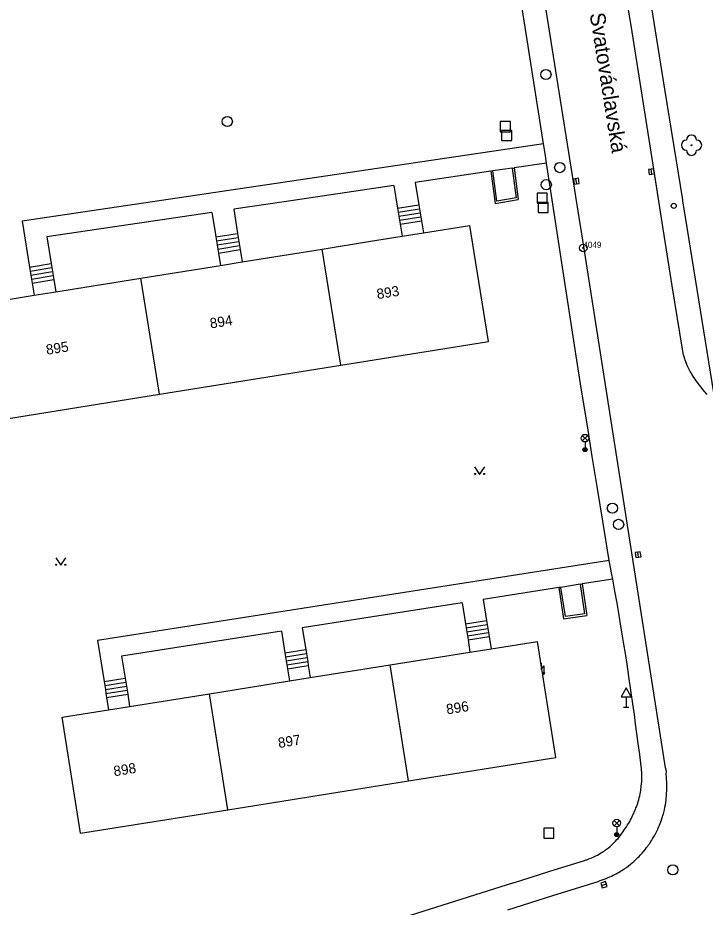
# Model space of a CAD drawing. Extents: x -539244 to -537359, y -1183785 to -1181851.
# Drawn here: x -537658.7 to -537591.1, y -1182068.9 to -1181981.5 of the extents above; entities that cross this region are included whole.
import ezdxf

# ---------------------------------------------------------------- set-up
doc = ezdxf.new("R2010")
doc.units = 0
for name, color, linetype in [('Vrstva 10', 7, 'Continuous'), ('Vrstva 11', 7, 'Continuous'), ('Vrstva 21', 7, 'Continuous'), ('Vrstva 22', 7, 'Continuous'), ('Vrstva 23', 7, 'Continuous'), ('Vrstva 24', 7, 'Continuous'), ('Vrstva 26', 7, 'Continuous'), ('Vrstva 27', 7, 'Continuous'), ('Vrstva 28', 7, 'Continuous'), ('Vrstva 33', 7, 'Continuous'), ('Vrstva 34', 7, 'Continuous'), ('Vrstva 36', 7, 'Continuous'), ('Vrstva 47', 7, 'Continuous'), ('Vrstva 49', 7, 'Continuous'), ('Vrstva 5', 7, 'Continuous'), ('Vrstva 7', 7, 'Continuous')]:
    doc.layers.add(name, color=color, linetype=linetype)

msp = doc.modelspace()

# ---------------------------------------------------------------- linework, layer by layer
at = {"layer": 'Vrstva 10'}
for p, q in [((-537598.321, -1181982.879), (-537600.408, -1181969.81)), ((-537604.08, -1181997.63), (-537607.495, -1181976.195)), ((-537596.931, -1181991.591), (-537598.321, -1181982.879)), ((-537596.14, -1181996.57), (-537596.931, -1181991.591)), ((-537594.356, -1182007.847), (-537595.341, -1182001.615)), ((-537599.455, -1182026.989), (-537603.168, -1182003.365)), ((-537593.37, -1182014.08), (-537594.356, -1182007.847)), ((-537595.733, -1182050.613), (-537599.455, -1182026.989)), ((-537595.024, -1182055.239), (-537595.733, -1182050.613))]:
    msp.add_line(p, q, dxfattribs=at)
for points in [[(-537595.341, -1182001.615), (-537595.74, -1181999.092), (-537596.14, -1181996.57)], [(-537603.168, -1182003.365), (-537603.335, -1182002.313), (-537603.393, -1182001.946), (-537603.624, -1182000.497), (-537604.08, -1181997.63)], [(-537590.921, -1182018.529), (-537591.144, -1182018.275), (-537591.348, -1182018.035), (-537591.534, -1182017.808), (-537591.703, -1182017.595), (-537591.856, -1182017.393), (-537591.996, -1182017.202), (-537592.122, -1182017.021), (-537592.237, -1182016.851), (-537592.34, -1182016.69), (-537592.434, -1182016.538), (-537592.519, -1182016.394), (-537592.596, -1182016.258), (-537592.665, -1182016.13), (-537592.728, -1182016.009), (-537592.785, -1182015.895), (-537592.887, -1182015.679), (-537592.969, -1182015.488), (-537593.036, -1182015.318), (-537593.092, -1182015.169), (-537593.137, -1182015.037), (-537593.174, -1182014.92), (-537593.234, -1182014.714), (-537593.274, -1182014.558), (-537593.302, -1182014.44), (-537593.338, -1182014.261), (-537593.37, -1182014.08)], [(-537595.004, -1182058.627), (-537594.976, -1182058.416), (-537594.954, -1182058.217), (-537594.936, -1182058.031), (-537594.923, -1182057.857), (-537594.913, -1182057.694), (-537594.906, -1182057.54), (-537594.898, -1182057.253), (-537594.897, -1182057.001), (-537594.901, -1182056.781), (-537594.907, -1182056.589), (-537594.915, -1182056.42), (-537594.933, -1182056.125), (-537594.951, -1182055.903), (-537594.94, -1182055.55), (-537595.024, -1182055.239)], [(-537601.045, -1182066.175), (-537600.856, -1182066.101), (-537600.675, -1182066.025), (-537600.501, -1182065.948), (-537600.333, -1182065.87), (-537600.173, -1182065.792), (-537600.019, -1182065.713), (-537599.871, -1182065.635), (-537599.729, -1182065.556), (-537599.592, -1182065.478), (-537599.461, -1182065.399), (-537599.335, -1182065.321), (-537599.215, -1182065.244), (-537599.099, -1182065.167), (-537598.877, -1182065.013), (-537598.673, -1182064.862), (-537598.484, -1182064.715), (-537598.311, -1182064.573), (-537598.151, -1182064.435), (-537598.003, -1182064.302), (-537597.866, -1182064.174), (-537597.74, -1182064.051), (-537597.624, -1182063.933), (-537597.516, -1182063.82), (-537597.417, -1182063.712), (-537597.324, -1182063.609), (-537597.155, -1182063.411), (-537597.01, -1182063.232), (-537596.885, -1182063.073), (-537596.779, -1182062.93), (-537596.687, -1182062.802), (-537596.608, -1182062.689), (-537596.473, -1182062.487), (-537596.374, -1182062.332), (-537596.301, -1182062.214), (-537596.194, -1182062.034), (-537596.09, -1182061.85), (-537595.979, -1182061.644), (-537595.877, -1182061.444), (-537595.785, -1182061.251), (-537595.7, -1182061.064), (-537595.622, -1182060.882), (-537595.551, -1182060.706), (-537595.486, -1182060.536), (-537595.427, -1182060.371), (-537595.373, -1182060.21), (-537595.324, -1182060.055), (-537595.279, -1182059.905), (-537595.238, -1182059.76), (-537595.201, -1182059.619), (-537595.167, -1182059.482), (-537595.137, -1182059.35), (-537595.083, -1182059.093), (-537595.039, -1182058.853), (-537595.004, -1182058.627)], [(-537610.52, -1182069.18), (-537606.09, -1182067.785), (-537601.66, -1182066.39), (-537601.447, -1182066.32), (-537601.242, -1182066.249), (-537601.045, -1182066.175)]]:
    msp.add_lwpolyline(points, dxfattribs=at)
at = {"layer": 'Vrstva 11'}
for p, q in [((-537608.814, -1181982.429), (-537609.977, -1181975.131)), ((-537595.086, -1181988.527), (-537597.11, -1181975.95)), ((-537608.155, -1181986.6), (-537608.814, -1181982.429)), ((-537607.01, -1181993.91), (-537658.271, -1182001.498)), ((-537606.73, -1181995.78), (-537609.904, -1181996.25)), ((-537612.2, -1181996.59), (-537619.625, -1181997.689)), ((-537610.102, -1181996.279), (-537612.002, -1181996.561)), ((-537619.625, -1181997.689), (-537619.274, -1181999.876)), ((-537621.724, -1181998), (-537632.52, -1181999.598)), ((-537621.724, -1181998), (-537621.369, -1182000.212)), ((-537632.52, -1181999.598), (-537637.473, -1182000.331)), ((-537637.473, -1182000.331), (-537637.093, -1182002.704)), ((-537621.369, -1182000.212), (-537619.274, -1181999.876)), ((-537621.305, -1182000.606), (-537619.21, -1182000.27)), ((-537639.629, -1182000.65), (-537655.843, -1182003.051)), ((-537639.629, -1182000.65), (-537639.32, -1182002.575)), ((-537621.242, -1182001.001), (-537619.147, -1182000.665)), ((-537621.178, -1182001.396), (-537619.083, -1182001.06)), ((-537591.591, -1182010.248), (-537593.062, -1182001.105)), ((-537658.271, -1182001.498), (-537657.548, -1182006.006)), ((-537621.115, -1182001.791), (-537619.02, -1182001.455)), ((-537655.843, -1182003.051), (-537655.424, -1182005.665)), ((-537639.32, -1182002.575), (-537639.244, -1182003.049)), ((-537639.244, -1182003.049), (-537637.093, -1182002.704)), ((-537639.181, -1182003.443), (-537637.029, -1182003.098)), ((-537639.118, -1182003.838), (-537636.966, -1182003.493)), ((-537639.054, -1182004.233), (-537636.903, -1182003.888)), ((-537604.904, -1182007.716), (-537605.491, -1182003.885)), ((-537638.991, -1182004.628), (-537636.839, -1182004.283)), ((-537657.548, -1182006.006), (-537655.424, -1182005.665)), ((-537657.484, -1182006.4), (-537655.36, -1182006.059)), ((-537657.421, -1182006.795), (-537655.297, -1182006.454)), ((-537657.357, -1182007.19), (-537655.236, -1182006.843)), ((-537657.294, -1182007.585), (-537655.17, -1182007.244)), ((-537590.12, -1182019.39), (-537591.591, -1182010.248)), ((-537600.57, -1182034.84), (-537650.874, -1182042.716)), ((-537603.406, -1182037.189), (-537605.322, -1182037.489)), ((-537600.22, -1182036.69), (-537603.209, -1182037.158)), ((-537605.52, -1182037.52), (-537612.954, -1182038.684)), ((-537612.954, -1182038.684), (-537612.624, -1182040.753)), ((-537615.029, -1182039.009), (-537620.698, -1182039.896)), ((-537615.029, -1182039.009), (-537614.698, -1182041.084)), ((-537620.698, -1182039.896), (-537630.737, -1182041.468)), ((-537630.737, -1182041.468), (-537630.399, -1182043.588)), ((-537614.698, -1182041.084), (-537612.624, -1182040.753)), ((-537614.634, -1182041.479), (-537612.56, -1182041.148)), ((-537614.571, -1182041.874), (-537612.497, -1182041.543)), ((-537632.794, -1182041.79), (-537648.503, -1182044.249)), ((-537632.794, -1182041.79), (-537632.455, -1182043.916)), ((-537614.508, -1182042.269), (-537612.434, -1182041.938)), ((-537614.445, -1182042.664), (-537612.371, -1182042.333)), ((-537650.874, -1182042.716), (-537650.23, -1182046.751)), ((-537632.455, -1182043.916), (-537630.399, -1182043.588)), ((-537632.391, -1182044.311), (-537630.335, -1182043.983)), ((-537648.503, -1182044.249), (-537648.156, -1182046.42)), ((-537632.328, -1182044.706), (-537630.272, -1182044.378)), ((-537632.265, -1182045.101), (-537630.209, -1182044.773)), ((-537632.202, -1182045.496), (-537630.146, -1182045.168)), ((-537650.23, -1182046.751), (-537648.156, -1182046.42)), ((-537650.166, -1182047.146), (-537648.092, -1182046.815)), ((-537650.103, -1182047.541), (-537648.029, -1182047.21)), ((-537650.04, -1182047.936), (-537647.966, -1182047.605)), ((-537649.977, -1182048.331), (-537647.903, -1182048)), ((-537609.98, -1182066.54), (-537632.97, -1182073.77))]:
    msp.add_line(p, q, dxfattribs=at)
for points in [[(-537606.869, -1181994.845), (-537607.01, -1181993.91), (-537607.406, -1181991.367), (-537608.155, -1181986.6)], [(-537593.062, -1182001.105), (-537593.318, -1181999.513), (-537593.335, -1181999.41), (-537595.086, -1181988.527)], [(-537605.491, -1182003.885), (-537606.112, -1181999.833), (-537606.73, -1181995.78), (-537606.869, -1181994.845)], [(-537621.369, -1182000.212), (-537621.305, -1182000.606), (-537621.242, -1182001.001), (-537621.178, -1182001.396), (-537621.115, -1182001.791), (-537620.925, -1182002.977)], [(-537619.274, -1181999.876), (-537619.21, -1182000.27), (-537619.147, -1182000.665), (-537619.083, -1182001.06), (-537619.02, -1182001.455), (-537618.831, -1182002.641)], [(-537639.244, -1182003.049), (-537639.181, -1182003.443), (-537639.118, -1182003.838), (-537639.054, -1182004.233), (-537638.991, -1182004.628), (-537638.796, -1182005.843)], [(-537637.093, -1182002.704), (-537637.029, -1182003.098), (-537636.966, -1182003.493), (-537636.903, -1182003.888), (-537636.839, -1182004.283), (-537636.644, -1182005.498)], [(-537655.424, -1182005.665), (-537655.36, -1182006.059), (-537655.297, -1182006.454), (-537655.236, -1182006.843), (-537655.17, -1182007.244), (-537654.979, -1182008.439)], [(-537657.548, -1182006.006), (-537657.484, -1182006.4), (-537657.421, -1182006.795), (-537657.357, -1182007.19), (-537657.294, -1182007.585), (-537657.103, -1182008.78)], [(-537602.646, -1182022.036), (-537603.37, -1182017.501), (-537603.908, -1182014.098), (-537604.308, -1182011.545), (-537604.904, -1182007.716)], [(-537600.57, -1182034.84), (-537601.201, -1182030.973), (-537601.751, -1182027.589), (-537602.229, -1182024.628), (-537602.646, -1182022.036)], [(-537598.807, -1182045.042), (-537598.969, -1182043.996), (-537599.114, -1182043.08), (-537599.244, -1182042.28), (-537599.476, -1182040.88), (-537599.655, -1182039.831), (-537599.793, -1182039.045), (-537600.003, -1182037.867), (-537600.22, -1182036.69), (-537600.309, -1182036.228), (-537600.445, -1182035.535), (-537600.51, -1182035.188), (-537600.57, -1182034.84)], [(-537614.698, -1182041.084), (-537614.634, -1182041.479), (-537614.571, -1182041.874), (-537614.508, -1182042.269), (-537614.445, -1182042.664), (-537614.256, -1182043.858)], [(-537612.624, -1182040.753), (-537612.56, -1182041.148), (-537612.497, -1182041.543), (-537612.434, -1182041.938), (-537612.371, -1182042.333), (-537612.182, -1182043.527)], [(-537632.455, -1182043.916), (-537632.391, -1182044.311), (-537632.328, -1182044.706), (-537632.265, -1182045.101), (-537632.202, -1182045.496), (-537632.012, -1182046.69)], [(-537630.399, -1182043.588), (-537630.335, -1182043.983), (-537630.272, -1182044.378), (-537630.209, -1182044.773), (-537630.146, -1182045.168), (-537629.957, -1182046.363)], [(-537597.42, -1182055.08), (-537597.565, -1182053.931), (-537597.704, -1182052.853), (-537597.837, -1182051.841), (-537597.965, -1182050.893), (-537598.086, -1182050.004), (-537598.202, -1182049.17), (-537598.425, -1182047.607), (-537598.626, -1182046.239), (-537598.807, -1182045.042)], [(-537650.23, -1182046.751), (-537650.166, -1182047.146), (-537650.103, -1182047.541), (-537650.04, -1182047.936), (-537649.977, -1182048.331), (-537649.787, -1182049.526)], [(-537648.156, -1182046.42), (-537648.092, -1182046.815), (-537648.029, -1182047.21), (-537647.966, -1182047.605), (-537647.903, -1182048), (-537647.713, -1182049.195)], [(-537600.72, -1182063.16), (-537600.633, -1182063.09), (-537600.47, -1182062.953), (-537600.329, -1182062.829), (-537600.208, -1182062.715), (-537600.103, -1182062.612), (-537600.012, -1182062.519), (-537599.933, -1182062.436), (-537599.797, -1182062.285), (-537599.696, -1182062.168), (-537599.621, -1182062.078), (-537599.509, -1182061.939), (-537599.399, -1182061.795), (-537599.251, -1182061.593), (-537599.113, -1182061.397), (-537598.984, -1182061.206), (-537598.863, -1182061.021), (-537598.751, -1182060.841), (-537598.647, -1182060.666), (-537598.55, -1182060.497), (-537598.459, -1182060.332), (-537598.375, -1182060.172), (-537598.296, -1182060.017), (-537598.223, -1182059.866), (-537598.155, -1182059.72), (-537598.092, -1182059.578), (-537598.033, -1182059.44), (-537597.979, -1182059.307), (-537597.928, -1182059.177), (-537597.881, -1182059.052), (-537597.795, -1182058.808), (-537597.722, -1182058.578), (-537597.66, -1182058.363), (-537597.606, -1182058.16), (-537597.561, -1182057.97), (-537597.522, -1182057.791), (-537597.49, -1182057.624), (-537597.462, -1182057.466), (-537597.44, -1182057.318), (-537597.421, -1182057.18), (-537597.405, -1182057.049), (-537597.381, -1182056.805), (-537597.367, -1182056.59), (-537597.358, -1182056.402), (-537597.355, -1182056.238), (-537597.354, -1182056.094), (-537597.359, -1182055.841), (-537597.368, -1182055.651), (-537597.377, -1182055.508), (-537597.396, -1182055.294), (-537597.42, -1182055.08)], [(-537609.98, -1182066.54), (-537606.49, -1182065.435), (-537603, -1182064.33), (-537602.869, -1182064.288), (-537602.77, -1182064.26), (-537602.505, -1182064.157), (-537602.284, -1182064.068), (-537602.08, -1182063.979), (-537601.892, -1182063.891), (-537601.719, -1182063.803), (-537601.558, -1182063.716), (-537601.41, -1182063.63), (-537601.272, -1182063.546), (-537601.145, -1182063.464), (-537601.027, -1182063.385), (-537600.917, -1182063.307), (-537600.815, -1182063.232), (-537600.72, -1182063.16)]]:
    msp.add_lwpolyline(points, dxfattribs=at)
at = {"layer": 'Vrstva 21'}
for radius in [0.375, 0.05]:
    msp.add_circle((-537603.11, -1182004.12), radius, dxfattribs=at)
at = {"layer": 'Vrstva 22'}
msp.add_circle((-537592.47, -1181994.03), 0.05, dxfattribs=at)
for centre, start, end in [((-537592.47, -1181993.53), 0, 180), ((-537592.97, -1181994.03), 90, 270), ((-537591.97, -1181994.03), 270, 90), ((-537592.47, -1181994.53), 180, 0)]:
    msp.add_arc(centre, 0.5, start, end, dxfattribs=at)
at = {"layer": 'Vrstva 24'}
for p, q in [((-537607.25, -1182044.944), (-537607.25, -1182045.571)), ((-537607.25, -1182045.571), (-537607, -1182045.195)), ((-537607.109, -1182045.825), (-537607, -1182046.07)), ((-537607, -1182045.195), (-537607, -1182046.07)), ((-537607, -1182046.07), (-537606.889, -1182045.825))]:
    msp.add_line(p, q, dxfattribs=at)
at = {"layer": 'Vrstva 26'}
for points in [[(-537611.269, -1181992.71), (-537610.27, -1181992.709), (-537610.271, -1181991.71), (-537611.27, -1181991.711)], [(-537611.139, -1181993.58), (-537610.14, -1181993.579), (-537610.141, -1181992.58), (-537611.14, -1181992.581)], [(-537607.649, -1181999.73), (-537606.65, -1181999.729), (-537606.651, -1181998.73), (-537607.65, -1181998.731)], [(-537607.559, -1182000.66), (-537606.56, -1182000.659), (-537606.561, -1181999.66), (-537607.56, -1181999.661)], [(-537606.989, -1182062.149), (-537605.991, -1182062.149), (-537605.991, -1182061.149), (-537606.989, -1182061.149)]]:
    msp.add_lwpolyline(points, close=True, dxfattribs=at)
at = {"layer": 'Vrstva 27'}
for p, q in [((-537596.37, -1181996.871), (-537596.448, -1181996.377)), ((-537603.758, -1181997.817), (-537603.836, -1181997.323)), ((-537597.681, -1182034.527), (-537597.759, -1182034.033)), ((-537601.316, -1182066.796), (-537600.84, -1182066.646))]:
    msp.add_line(p, q, dxfattribs=at)
for points in [[(-537596.123, -1181996.832), (-537596.201, -1181996.338), (-537596.695, -1181996.416), (-537596.617, -1181996.91)], [(-537603.511, -1181997.778), (-537603.589, -1181997.284), (-537604.083, -1181997.362), (-537604.005, -1181997.856)], [(-537597.434, -1182034.488), (-537597.512, -1182033.994), (-537598.006, -1182034.072), (-537597.928, -1182034.566)], [(-537601.241, -1182067.035), (-537600.764, -1182066.884), (-537600.915, -1182066.407), (-537601.392, -1182066.558)]]:
    msp.add_lwpolyline(points, close=True, dxfattribs=at)
for centre in [(-537606.78, -1181987.08), (-537638.11, -1181991.7), (-537605.43, -1181996.23), (-537606.75, -1181997.91), (-537600.25, -1182029.71), (-537599.64, -1182031.3), (-537594.3, -1182065.26)]:
    msp.add_circle(centre, 0.5, dxfattribs=at)
at = {"layer": 'Vrstva 28'}
msp.add_circle((-537594.22, -1181999.99), 0.25, dxfattribs=at)
at = {"layer": 'Vrstva 33'}
for p, q in [((-537603.205, -1182023.09), (-537602.675, -1182022.56)), ((-537603.205, -1182022.56), (-537602.675, -1182023.09)), ((-537602.94, -1182023.2), (-537602.94, -1182023.95)), ((-537600.085, -1182060.93), (-537599.555, -1182060.4)), ((-537600.085, -1182060.4), (-537599.555, -1182060.93)), ((-537599.82, -1182061.04), (-537599.82, -1182061.79))]:
    msp.add_line(p, q, dxfattribs=at)
for centre, radius in [((-537602.94, -1182022.825), 0.375), ((-537602.94, -1182023.95), 0.2), ((-537602.94, -1182023.95), 0.145), ((-537602.94, -1182023.95), 0.0876), ((-537599.82, -1182060.665), 0.375), ((-537599.82, -1182061.79), 0.2), ((-537599.82, -1182061.79), 0.145), ((-537599.82, -1182061.79), 0.0876)]:
    msp.add_circle(centre, radius, dxfattribs=at)
at = {"layer": 'Vrstva 34'}
for p, q in [((-537598.896, -1182048.246), (-537598.896, -1182049.264)), ((-537599.146, -1182049.264), (-537598.646, -1182049.264))]:
    msp.add_line(p, q, dxfattribs=at)
msp.add_lwpolyline([(-537599.396, -1182048.246), (-537598.396, -1182048.246), (-537598.896, -1182047.38)], close=True, dxfattribs=at)
at = {"layer": 'Vrstva 36'}
for points in [[(-537613.802, -1182025.647), (-537613.302, -1182026.397), (-537612.802, -1182025.647)], [(-537654.985, -1182034.574), (-537654.485, -1182035.324), (-537653.985, -1182034.574)]]:
    msp.add_lwpolyline(points, dxfattribs=at)
for centre in [(-537613.752, -1182026.347), (-537612.853, -1182026.347), (-537654.935, -1182035.274), (-537654.036, -1182035.274)]:
    msp.add_circle(centre, 0.05, dxfattribs=at)
at = {"layer": 'Vrstva 5'}
for p, q in [((-537613.842, -1182004.581), (-537614.27, -1182001.91)), ((-537626.955, -1182015.648), (-537628.785, -1182004.238)), ((-537612.44, -1182013.32), (-537613.842, -1182004.581)), ((-537644.787, -1182018.508), (-537646.617, -1182007.098)), ((-537626.955, -1182015.648), (-537612.44, -1182013.32)), ((-537644.787, -1182018.508), (-537626.955, -1182015.648)), ((-537659.835, -1182020.922), (-537644.787, -1182018.508)), ((-537605.8, -1182054.21), (-537607.62, -1182042.8)), ((-537620.287, -1182056.521), (-537622.107, -1182045.111)), ((-537638.043, -1182059.353), (-537639.863, -1182047.943)), ((-537652.55, -1182061.65), (-537654.34, -1182050.25)), ((-537620.287, -1182056.521), (-537605.8, -1182054.21)), ((-537638.043, -1182059.353), (-537620.287, -1182056.521)), ((-537652.55, -1182061.65), (-537638.043, -1182059.353))]:
    msp.add_line(p, q, dxfattribs=at)
for points in [[(-537620.925, -1182002.977), (-537618.831, -1182002.641), (-537614.27, -1182001.91)], [(-537661.665, -1182009.512), (-537657.103, -1182008.78), (-537654.979, -1182008.439), (-537646.617, -1182007.098), (-537638.796, -1182005.843), (-537636.644, -1182005.498), (-537628.785, -1182004.238), (-537624.04, -1182003.477), (-537620.925, -1182002.977)], [(-537622.107, -1182045.111), (-537614.256, -1182043.858), (-537612.182, -1182043.527), (-537607.62, -1182042.8)], [(-537639.863, -1182047.943), (-537632.012, -1182046.69), (-537629.957, -1182046.363), (-537622.107, -1182045.111)], [(-537654.34, -1182050.25), (-537649.787, -1182049.526), (-537647.713, -1182049.195), (-537639.863, -1182047.943)]]:
    msp.add_lwpolyline(points, dxfattribs=at)
at = {"layer": 'Vrstva 7'}
for p, q in [((-537610.102, -1181996.279), (-537609.723, -1181999.205)), ((-537603.406, -1182037.189), (-537602.976, -1182040.081))]:
    msp.add_line(p, q, dxfattribs=at)
for points in [[(-537612.002, -1181996.561), (-537612.2, -1181996.59), (-537611.79, -1181999.76), (-537609.5, -1181999.37)], [(-537609.723, -1181999.205), (-537611.618, -1181999.528), (-537612.002, -1181996.561)], [(-537610.102, -1181996.279), (-537609.904, -1181996.25), (-537609.5, -1181999.37)], [(-537603.406, -1182037.189), (-537603.209, -1182037.158), (-537602.75, -1182040.25)], [(-537605.322, -1182037.489), (-537605.52, -1182037.52), (-537605.04, -1182040.59), (-537602.75, -1182040.25)], [(-537602.976, -1182040.081), (-537604.873, -1182040.363), (-537605.322, -1182037.489)]]:
    msp.add_lwpolyline(points, dxfattribs=at)

# ---------------------------------------------------------------- texts
at = {"layer": 'Vrstva 23'}
msp.add_text('4049', height=0.6, dxfattribs=at).set_placement((-537603.11, -1182004.12))
at = {"layer": 'Vrstva 47'}
for s, rotation, p in [(' 893', 9.11182, (-537623.712, -1182009.229)), (' 894', 9.11182, (-537640.111, -1182012.108)), (' 895', 9.11182, (-537656.223, -1182014.698)), (' 896', 9.06286, (-537616.872, -1182050.044)), (' 897', 9.06286, (-537633.409, -1182053.346)), (' 898', 9.06286, (-537649.585, -1182056.123))]:
    msp.add_text(s, height=1, rotation=rotation, dxfattribs=at).set_placement(p)
at = {"layer": 'Vrstva 49'}
msp.add_text('ul. Svatováclavská', height=1.5, rotation=279.05222, dxfattribs=at).set_placement((-537602.908, -1181978.469))

doc.saveas('drawing.dxf')
